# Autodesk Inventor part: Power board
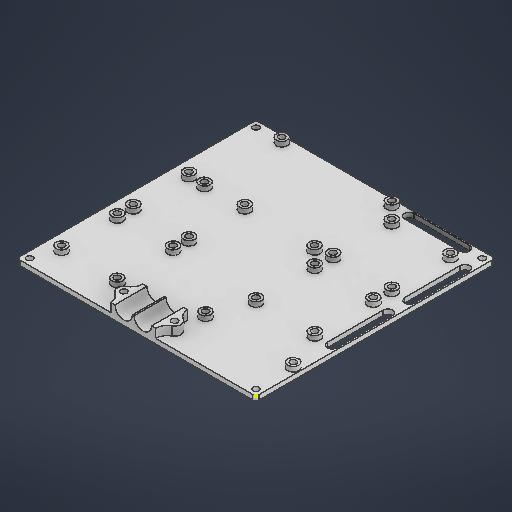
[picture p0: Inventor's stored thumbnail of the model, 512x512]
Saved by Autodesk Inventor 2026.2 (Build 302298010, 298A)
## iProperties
Created: 2026-04
Part Number: Power board
Material: 일반
Document SubType Name: Modeling
Designer: work
Density: 1 g/cm^3
Appearance: 기본값
Author: work
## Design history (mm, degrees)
sketch "스케치1"
  geometry: L1 (0, -150)-(150, -150); L2 (150, -150)-(150, 0); L3 (150, 0)-(0, 0); L4 (0, 0)-(0, -150); L5 (0, -150)-(150, 0); L6 (150, -150)-(0, 0); L7 (4, -4)-(146, -4); L8 (146, -4)-(146, -146); L9 (146, -146)-(4, -146); L10 (4, -146)-(4, -4); L11 (4, -4)-(146, -146); L12 (146, -4)-(4, -146); L13 (50.8, -99.2)-(50.8, -136); L14 (14, -99.2)-(50.8, -99.2); L15 (50.8, -136)-(14, -136); L16 (14, -136)-(14, -99.2); L17 (14, -99.2)-(50.8, -136); L18 (50.8, -99.2)-(14, -136); L19 (32.4, -117.6)-(32.4, -146); L20 (49.9, -143)-(14.9, -143); L21 (14.9, -146)-(49.9, -146); L22 (14.9, -149)-(49.9, -149); L23 (32.4, -69.232)-(4, -69.232); L24 (14, -87.632)-(14, -50.832); L25 (14, -50.832)-(50.8, -50.832); L26 (50.8, -87.632)-(14, -87.632); L27 (50.8, -50.832)-(14, -87.632); L28 (50.8, -50.832)-(50.8, -87.632); L29 (50.8, -87.632)-(14, -50.832); L30 (4, -86.732)-(4, -51.732); L31 (7, -86.732)-(7, -51.732); L32 (1, -51.732)-(1, -86.732); L33 (60.8, -146)-(60.8, -97.5); L34 (60.8, -97.5)-(129.8, -97.5); L35 (129.8, -146)-(60.8, -146); L36 (129.8, -97.5)-(60.8, -146); L37 (129.8, -97.5)-(129.8, -146); L38 (60.8, -97.5)-(129.8, -146); L39 (8.5, -13.832)-(54.5, -13.832); L40 (54.5, -13.832)-(8.5, -40.832); L41 (54.5, -13.832)-(54.5, -40.832); L42 (59, -27.332)-(4, -27.332); L43 (8.5, -13.832)-(54.5, -40.832); L44 (8.5, -40.832)-(8.5, -13.832); L45 (54.5, -40.832)-(8.5, -40.832); L46 (4, -135.1)-(4, -100.1); L47 (7, -135.1)-(7, -100.1); L48 (1, -100.1)-(1, -135.1); L49 (105, -18)-(140, -18); L50 (140, -18)-(140, -53); L51 (140, -53)-(105, -53); L52 (105, -53)-(105, -18); L53 (105, -18)-(140, -53); L54 (140, -18)-(105, -53); L55 (105, -35.5)-(140, -35.5); L56 (122.5, -53)-(122.5, -18); L57 (140, -98)-(105, -98); L58 (105, -80.5)-(140, -80.5); L59 (105, -63)-(140, -98); L60 (140, -63)-(140, -98); L61 (122.5, -98)-(122.5, -63); L62 (105, -98)-(105, -63); L63 (105, -63)-(140, -63); L64 (140, -63)-(105, -98); C1 r 2 at (50.8, -99.2); C2 r 2 at (14, -99.2); C3 r 2 at (14, -136); C4 r 2 at (50.8, -136); C5 r 2 at (14, -50.832); C6 r 2 at (14, -87.632); C7 r 2 at (50.8, -50.832); C8 r 2 at (50.8, -87.632); C9 r 2 at (60.8, -97.5); C10 r 2 at (129.8, -97.5); C11 r 2 at (60.8, -146); C12 r 2 at (129.8, -146); C13 r 2 at (59, -27.332); C14 r 2 at (4, -27.332); C15 r 2 at (4, -4); C16 r 2 at (4, -146); C17 r 2 at (146, -146); C18 r 2 at (146, -4); C19 r 2 at (140, -18); C20 r 2 at (140, -53); C21 r 2 at (105, -53); C22 r 2 at (105, -18); C23 r 2 at (140, -98); C24 r 2 at (105, -63); C25 r 2 at (140, -63); C26 r 2 at (105, -98); A1 r 3 centre (49.9, -146) between (49.9, -149) and (49.9, -143); A2 r 3 centre (14.9, -146) between (14.9, -143) and (14.9, -149); A3 r 3 centre (4, -51.732) between (7, -51.732) and (1, -51.732); A4 r 3 centre (4, -86.732) between (1, -86.732) and (7, -86.732); A5 r 3 centre (4, -135.1) between (1, -135.1) and (7, -135.1); A6 r 3 centre (4, -100.1) between (7, -100.1) and (1, -100.1); 8 further points
  constraints: 134 end point, 32 centre point, 29 midpoint, 27 coincident, 19 parallel, 12 point on circle, 12 tangent, 10 horizontal, 8 perpendicular, 7 point on line, 2 vertical, 1 collinear
  dimensions: "d0" = 150 distance of L3.end L2.end; "d1" = 150 distance of L2.end L1.end; "d2" = 4 distance between parallel lines of L2 L8; "d3" = 36.8 distance of L13.end L15.end; "d4" = 36.8 distance of L13.start L13.end; "d5" = 4 diameter of C2; "d6" = 4 diameter of C3; "d7" = 4 diameter of C4; "d8" = 4 diameter of C1; "d9" = 6 diameter of A1; "d10" = 35 distance of L21.start L21.end; "d11" = 10 horizontal distance of L9.end C3.centre; "d12" = 10 horizontal distance of L9.end L15.end; "d13" = 36.8 distance of L24.start L24.end; "d14" = 36.8 distance of L26.start L24.start; "d15" = 4 diameter of C7; "d16" = 4 diameter of C5; "d17" = 4 diameter of C6; "d18" = 4 diameter of C8; "d19" = 6 diameter of A3; "d20" = 35 distance of L30.start L30.end; "d21" = 28.4 distance of L23.start L23.end; "d22" = 69 distance of L35.start L33.start; "d23" = 48.5 distance of L34.end L35.start; "d24" = 4 diameter of C9; "d25" = 4 diameter of C11; "d26" = 4 diameter of C12; "d27" = 4 diameter of C10; "d28" = 10 distance between parallel lines of L13 L33; "d29" = 11.56791 distance between parallel lines of L14 L26; "d30" = 55 distance of L42.start L42.end; "d31" = 46 distance of L41.end L40.end; "d32" = 27 distance of L39.end L41.end; "d33" = 4 diameter of C13; "d34" = 4 diameter of C14; "d35" = 10 distance between parallel lines of L25 L45; "d36" = 4 diameter of C15; "d37" = 4 diameter of C16; "d38" = 4 diameter of C17; "d39" = 4 diameter of C18; "d40" = 17.5 distance of point (4, -117.6) L46.end; "d41" = 6 diameter of A6; "d48" = 35 distance of L50.end L51.end; "d49" = 35 distance of L49.end L50.end; "d50" = 14 distance between parallel lines of L7 L49; "d51" = 6 distance between parallel lines of L8 L50; "d52" = 4 diameter of C19; "d53" = 4 diameter of C20; "d54" = 4 diameter of C21; "d55" = 4 diameter of C22; "d56" = 35 distance of L57.start L57.end; "d57" = 35 distance of L60.start L57.start; "d58" = 4 diameter of C25; "d59" = 4 diameter of C23; "d60" = 4 diameter of C26; "d61" = 4 diameter of C24; "d62" = 10 distance between parallel lines of L63 L51
extrude "돌출1" new body sketch "스케치1" distance "d42" = 3; taper "d43" = 0 deg
sketch "스케치2"
  geometry: L1 (-7, 100.1)-(-7, 135.1) reference; L2 (-150, 150)-(-150, 0) reference; L3 (-150, 0)-(0, 0) reference; L4 (0, 0)-(0, 150) reference; L5 (0, 150)-(-150, 150) reference; L6 (-1, 135.1)-(-1, 100.1) reference; L7 (-7, 100.1)-(-7, 135.1) reference; L8 (-7, 51.732)-(-7, 86.732) reference; L9 (-1, 86.732)-(-1, 51.732) reference; L10 (-49.9, 149)-(-14.9, 149) reference; L11 (-14.9, 143)-(-49.9, 143) reference; C1 r 2 at (-146, 4) reference; C2 r 2 at (-4, 146) reference; C3 r 2 at (-4, 27.332) reference; C4 r 2 at (-129.8, 146) reference; C5 r 2 at (-129.8, 97.5) reference; C6 r 2 at (-50.8, 87.632) reference; C7 r 2 at (-50.8, 50.832) reference; C8 r 2 at (-14, 87.632) reference; C9 r 2 at (-14, 50.832) reference; C10 r 2 at (-50.8, 136) reference; C11 r 2 at (-14, 136) reference; C12 r 2 at (-14, 99.2) reference; C13 r 2 at (-50.8, 99.2) reference; C14 r 2 at (-60.8, 97.5) reference; C15 r 2 at (-60.8, 146) reference; C16 r 2 at (-59, 27.332) reference; C17 r 2 at (-4, 4) reference; C18 r 2 at (-146, 146) reference; C19 r 2 at (-14, 87.632) reference; C20 r 2 at (-14, 50.832) reference; C21 r 2 at (-129.8, 146) reference; C22 r 3.5 at (-4, 27.332); C23 r 2 at (-105, 18) reference; C24 r 2 at (-140, 18) reference; C25 r 2 at (-140, 53) reference; C26 r 2 at (-105, 53) reference; C27 r 2 at (-105, 63) reference; C28 r 2 at (-140, 63) reference; C29 r 2 at (-140, 98) reference; C30 r 2 at (-105, 98) reference; A1 r 3 centre (-4, 135.1) between (-1, 135.1) and (-7, 135.1) reference; A2 r 3 centre (-4, 100.1) between (-7, 100.1) and (-1, 100.1) reference; A3 r 3 centre (-4, 86.732) between (-1, 86.732) and (-7, 86.732) reference; A4 r 3 centre (-4, 51.732) between (-7, 51.732) and (-1, 51.732) reference; A5 r 3 centre (-14.9, 146) between (-14.9, 143) and (-14.9, 149) reference; A6 r 3 centre (-49.9, 146) between (-49.9, 149) and (-49.9, 143) reference; 23 further points
  constraints: 23 coincident, 1 centre point
  dimensions: "d44" = 7 diameter of C22
  node "투영된 루프1"
extrude "돌출2" join sketch "스케치2" distance "d45" = 3; taper "d46" = 0 deg
fillet "모깎기1" dims "d47" = 2
sketch "스케치3"
  geometry: 1 further point
sketch "스케치4"
  geometry: L1 (146, 3)-(146, 0) reference; L2 (0, 3)-(146, 3) reference; L3 (0, 0)-(0, 3) reference; L4 (0, 0)-(146, 0) reference; L5 (0, 3)-(146, 3) reference; L6 (146, 3)-(0, 3) reference; L7 (57, 3)-(57, 8.5); L8 (57, 8.5)-(85, 8.5); L9 (85, 8.5)-(85, 3); L10 (41, 6)-(45, 6) reference; L11 (41, 0)-(45, 0) reference; C1 r 5.5 at (65, 8.5); C2 r 5.5 at (77, 8.5); 10 further points
  constraints: 6 end point, 3 perpendicular, 2 centre point, 2 point on line, 2 tangent, 1 midpoint
  dimensions: "d63" = 11 diameter of C1; "d64" = 11 diameter of C2; "d65" = 12 distance of C2.centre C1.centre; "d66" = 8 distance from line of L9 C2.centre; "d67" = 8 distance of L7.end C1.centre; "d68" = 28 distance of L7.end L8.end; "d69" = 14 distance from line of point (43, 6) L7
extrude "돌출3" join sketch "스케치4" distance "d70" = 20; taper "d71" = 0 deg
sketch "스케치5" dims "d76" = 8
  geometry: L1 (0, 0)-(0, 20) reference; L2 (0, 10)-(28, 10); L3 (28, 20)-(28, 0) reference; L4 (-2, 10)-(30, 10); L5 (25.5, 20)-(28, 20) reference; L6 (28, 0)-(28, 20) reference; L7 (-57, 0)-(89, 0) reference; L8 (14, 0)-(14, 20); L9 (14.5, 0)-(14.5, 20) reference; L10 (13.5, 20)-(14.5, 20) reference; C1 r 2 at (-2, 10); C2 r 2 at (30, 10); C3 r 4 at (-2, 10); A1 r 7.333 centre (35.333, 20) between (28, 20) and (31.882, 13.529); A2 r 7.333 centre (35.333, 0) between (31.882, 6.471) and (28, 0); A3 r 7.333 centre (-7.333, 0) between (0, 0) and (-3.882, 6.471); A4 r 7.333 centre (-7.333, 20) between (-3.882, 13.529) and (0, 20); 8 further points
  constraints: 8 point on circle, 7 centre point, 6 end point, 6 symmetric about line, 5 midpoint, 2 coincident, 1 collinear, 1 parallel, 1 point on line, 1 tangent, 7 other
  dimensions: "d72" = 4 diameter of C1; "d73" = 4 diameter of C2; "d74" = 32 distance of L4.end L4.start; "d75" = 8 diameter of C3
extrude "돌출4" join sketch "스케치5" stored distance "d77" = 0; taper "d78" = 0 deg
node "솔리드1"
feature "스케치 연계 패턴1"
node "투영된 루프2"
node "투영된 루프3"
